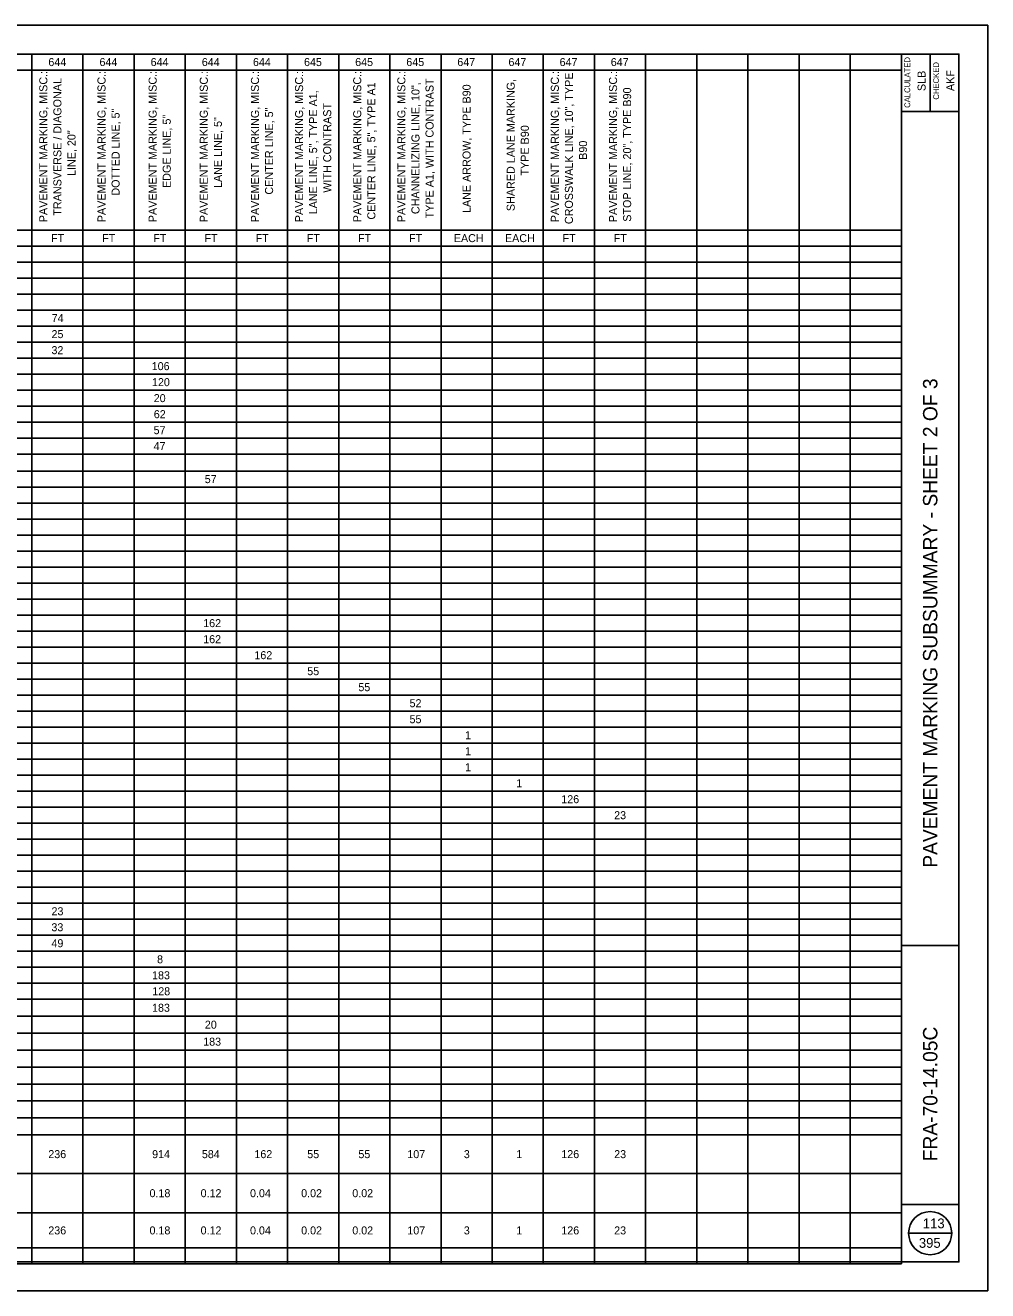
# Model space of a CAD drawing. Extents: x 1822379 to 1824724, y 710341 to 711455.
# Drawn here: x 1822396.38 to 1822413.11, y 711198.87 to 711220.87 of the extents above; entities that cross this region are included whole.
import ezdxf

# ---------------------------------------------------------------- set-up
doc = ezdxf.new("R2010")
doc.units = 0
for name, color, linetype in [('SH_Border', 7, 'Continuous'), ('SH_Cut_Line', 7, 'Continuous'), ('SH_Data', 7, 'Continuous'), ('SH_Text', 7, 'Continuous'), ('TX_P_20', 7, 'Continuous')]:
    doc.layers.add(name, color=color, linetype=linetype)

msp = doc.modelspace()

# ---------------------------------------------------------------- linework, layer by layer
at = {"layer": 'SH_Border'}
for p, q in [((1822411.613, 711199.366), (1822411.613, 711220.366)), ((1822412.113, 711220.366), (1822412.113, 711219.366)), ((1822411.613, 711219.366), (1822412.613, 711219.366)), ((1822411.613, 711204.866), (1822412.613, 711204.866)), ((1822411.613, 711200.366), (1822412.613, 711200.366))]:
    msp.add_line(p, q, dxfattribs=at)
msp.add_lwpolyline([(1822381.113, 711220.366), (1822412.613, 711220.366), (1822412.613, 711199.366), (1822381.113, 711199.366)], close=True, dxfattribs=at)
at = {"layer": 'SH_Cut_Line'}
msp.add_lwpolyline([(1822379.113, 711198.866), (1822413.113, 711198.866), (1822413.113, 711220.866), (1822379.113, 711220.866)], close=True, dxfattribs=at)
at = {"layer": 'SH_Data'}
for p, q in [((1822381.113, 711220.366), (1822411.613, 711220.366)), ((1822396.494, 711220.366), (1822396.494, 711199.333)), ((1822397.384, 711220.366), (1822397.384, 711199.333)), ((1822398.273, 711220.366), (1822398.273, 711199.333)), ((1822399.162, 711220.366), (1822399.162, 711199.333)), ((1822400.052, 711220.366), (1822400.052, 711199.333)), ((1822400.941, 711220.366), (1822400.941, 711199.333)), ((1822401.83, 711220.366), (1822401.83, 711199.333)), ((1822402.719, 711220.366), (1822402.719, 711199.333)), ((1822403.609, 711220.366), (1822403.609, 711199.333)), ((1822404.498, 711220.366), (1822404.498, 711199.333)), ((1822405.387, 711220.366), (1822405.387, 711199.333)), ((1822406.277, 711220.366), (1822406.277, 711199.333)), ((1822407.166, 711220.366), (1822407.166, 711199.333)), ((1822408.055, 711220.366), (1822408.055, 711199.333)), ((1822408.945, 711220.366), (1822408.945, 711199.333)), ((1822409.834, 711220.366), (1822409.834, 711199.333)), ((1822410.723, 711220.366), (1822410.723, 711199.333)), ((1822411.613, 711220.366), (1822411.613, 711199.333)), ((1822390.269, 711220.087), (1822411.613, 711220.087)), ((1822390.269, 711217.305), (1822411.613, 711217.305)), ((1822381.113, 711217.027), (1822411.613, 711217.027)), ((1822381.113, 711216.748), (1822411.613, 711216.748)), ((1822381.113, 711216.47), (1822411.613, 711216.47)), ((1822381.113, 711216.192), (1822411.613, 711216.192)), ((1822381.113, 711215.913), (1822411.613, 711215.913)), ((1822381.113, 711215.635), (1822411.613, 711215.635)), ((1822381.113, 711215.357), (1822411.613, 711215.357)), ((1822381.113, 711215.079), (1822411.613, 711215.079)), ((1822381.113, 711214.8), (1822411.613, 711214.8)), ((1822381.113, 711214.522), (1822411.613, 711214.522)), ((1822381.113, 711214.244), (1822411.613, 711214.244)), ((1822381.113, 711213.966), (1822411.613, 711213.966)), ((1822381.113, 711213.687), (1822411.613, 711213.687)), ((1822381.113, 711213.409), (1822411.613, 711213.409)), ((1822381.113, 711213.115), (1822411.613, 711213.115)), ((1822381.113, 711212.836), (1822411.613, 711212.836)), ((1822381.113, 711212.558), (1822411.613, 711212.558)), ((1822381.113, 711212.28), (1822411.613, 711212.28)), ((1822381.113, 711212.002), (1822411.613, 711212.002)), ((1822381.113, 711211.723), (1822411.613, 711211.723)), ((1822381.113, 711211.445), (1822411.613, 711211.445)), ((1822381.113, 711211.167), (1822411.613, 711211.167)), ((1822381.113, 711210.889), (1822411.613, 711210.889)), ((1822381.113, 711210.61), (1822411.613, 711210.61)), ((1822381.113, 711210.332), (1822411.613, 711210.332)), ((1822381.113, 711210.054), (1822411.613, 711210.054)), ((1822381.113, 711209.776), (1822411.613, 711209.776)), ((1822381.113, 711209.497), (1822411.613, 711209.497)), ((1822381.113, 711209.219), (1822411.613, 711209.219)), ((1822381.113, 711208.941), (1822411.613, 711208.941)), ((1822381.113, 711208.663), (1822411.613, 711208.663)), ((1822381.113, 711208.384), (1822411.613, 711208.384)), ((1822381.113, 711208.106), (1822411.613, 711208.106)), ((1822381.113, 711207.828), (1822411.613, 711207.828)), ((1822381.113, 711207.55), (1822411.613, 711207.55)), ((1822381.113, 711207.271), (1822411.613, 711207.271)), ((1822381.113, 711206.993), (1822411.613, 711206.993)), ((1822381.113, 711206.715), (1822411.613, 711206.715)), ((1822381.113, 711206.436), (1822411.613, 711206.436)), ((1822381.113, 711206.158), (1822411.613, 711206.158)), ((1822381.113, 711205.88), (1822411.613, 711205.88)), ((1822381.113, 711205.602), (1822411.613, 711205.602)), ((1822381.113, 711205.323), (1822411.613, 711205.323)), ((1822381.113, 711205.045), (1822411.613, 711205.045)), ((1822381.113, 711204.767), (1822411.613, 711204.767)), ((1822381.113, 711204.489), (1822411.613, 711204.489)), ((1822381.113, 711204.21), (1822411.613, 711204.21)), ((1822381.113, 711203.932), (1822411.613, 711203.932)), ((1822381.113, 711203.638), (1822411.613, 711203.638)), ((1822381.113, 711203.343), (1822411.613, 711203.343)), ((1822381.113, 711203.048), (1822411.613, 711203.048)), ((1822381.113, 711202.754), (1822411.613, 711202.754)), ((1822381.113, 711202.459), (1822411.613, 711202.459)), ((1822381.113, 711202.164), (1822411.613, 711202.164)), ((1822381.113, 711201.87), (1822411.613, 711201.87)), ((1822381.113, 711201.575), (1822411.613, 711201.575)), ((1822381.113, 711200.904), (1822411.613, 711200.904)), ((1822381.113, 711200.217), (1822411.613, 711200.217)), ((1822411.738, 711199.866), (1822412.488, 711199.866)), ((1822381.113, 711199.611), (1822411.613, 711199.611)), ((1822381.113, 711199.333), (1822411.613, 711199.333))]:
    msp.add_line(p, q, dxfattribs=at)
msp.add_circle((1822412.113, 711199.866), 0.375, dxfattribs=at)

# ---------------------------------------------------------------- texts
for s, height, p in [('CALCULATED', 0.1, (1822411.765, 711219.43)), ('CHECKED', 0.1, (1822412.265, 711219.573)), ('SLB', 0.14, (1822412.033, 711219.722)), ('AKF', 0.14, (1822412.533, 711219.723)), ('PAVEMENT MARKING SUBSUMMARY - SHEET 2 OF 3', 0.25, (1822412.238, 711206.219)), ('FRA-70-14.05C', 0.25, (1822412.238, 711201.115))]:
    msp.add_text(s, height=height, rotation=90, dxfattribs=at).set_placement(p)
at = {"layer": 'SH_Text'}
for s, height, p in [('644', 0.1391, (1822396.782, 711220.157)), ('644', 0.1391, (1822397.671, 711220.157)), ('644', 0.1391, (1822398.56, 711220.157)), ('644', 0.1391, (1822399.45, 711220.157)), ('644', 0.1391, (1822400.339, 711220.157)), ('645', 0.1391, (1822401.227, 711220.157)), ('645', 0.1391, (1822402.116, 711220.157)), ('645', 0.1391, (1822403.005, 711220.157)), ('647', 0.1391, (1822403.892, 711220.157)), ('647', 0.1391, (1822404.781, 711220.157)), ('647', 0.1391, (1822405.67, 711220.157)), ('647', 0.1391, (1822406.56, 711220.157)), ('FT', 0.1391, (1822396.829, 711217.096)), ('FT', 0.1391, (1822397.718, 711217.096)), ('FT', 0.1391, (1822398.607, 711217.096)), ('FT', 0.1391, (1822399.497, 711217.096)), ('FT', 0.1391, (1822400.386, 711217.096)), ('FT', 0.1391, (1822401.275, 711217.096)), ('FT', 0.1391, (1822402.165, 711217.096)), ('FT', 0.1391, (1822403.054, 711217.096)), ('EACH', 0.1391, (1822403.832, 711217.096)), ('EACH', 0.1391, (1822404.721, 711217.096)), ('FT', 0.1391, (1822405.722, 711217.096)), ('FT', 0.1391, (1822406.611, 711217.096)), ('74', 0.1391, (1822396.839, 711215.705)), ('25', 0.1391, (1822396.837, 711215.427)), ('32', 0.1391, (1822396.836, 711215.148)), ('106', 0.1391, (1822398.579, 711214.87)), ('120', 0.1391, (1822398.584, 711214.592)), ('20', 0.1391, (1822398.614, 711214.314)), ('62', 0.1391, (1822398.615, 711214.035)), ('57', 0.1391, (1822398.612, 711213.757)), ('47', 0.1391, (1822398.611, 711213.479)), ('57', 0.1391, (1822399.501, 711212.906)), ('162', 0.1391, (1822399.474, 711210.402)), ('162', 0.1391, (1822399.474, 711210.123)), ('162', 0.1391, (1822400.364, 711209.845)), ('55', 0.1391, (1822401.283, 711209.567)), ('55', 0.1391, (1822402.172, 711209.289)), ('52', 0.1391, (1822403.062, 711209.01)), ('55', 0.1391, (1822403.061, 711208.732)), ('1', 0.139, (1822404.027, 711208.454)), ('1', 0.139, (1822404.027, 711208.176)), ('1', 0.139, (1822404.027, 711207.897)), ('1', 0.139, (1822404.917, 711207.619)), ('126', 0.1391, (1822405.7, 711207.341)), ('23', 0.1391, (1822406.619, 711207.063)), ('23', 0.1391, (1822396.837, 711205.393)), ('33', 0.1391, (1822396.835, 711205.115)), ('49', 0.1391, (1822396.836, 711204.837)), ('8', 0.139, (1822398.672, 711204.558)), ('183', 0.1391, (1822398.585, 711204.28)), ('128', 0.1391, (1822398.589, 711204.002)), ('183', 0.1391, (1822398.585, 711203.715)), ('20', 0.1391, (1822399.503, 711203.421)), ('183', 0.1391, (1822399.474, 711203.126)), ('236', 0.1391, (1822396.781, 711201.17)), ('914', 0.1391, (1822398.586, 711201.17)), ('584', 0.1391, (1822399.451, 711201.17)), ('162', 0.1391, (1822400.364, 711201.17)), ('55', 0.1391, (1822401.283, 711201.17)), ('55', 0.1391, (1822402.172, 711201.17)), ('107', 0.1391, (1822403.023, 711201.17)), ('3', 0.139, (1822404.005, 711201.17)), ('1', 0.139, (1822404.917, 711201.17)), ('126', 0.1391, (1822405.7, 711201.17)), ('23', 0.1391, (1822406.619, 711201.17)), ('0.18', 0.1391, (1822398.541, 711200.491)), ('0.12', 0.1391, (1822399.429, 711200.491)), ('0.04', 0.1391, (1822400.288, 711200.491)), ('0.02', 0.1391, (1822401.177, 711200.491)), ('0.02', 0.1391, (1822402.066, 711200.491)), ('236', 0.1391, (1822396.781, 711199.844)), ('0.18', 0.1391, (1822398.541, 711199.844)), ('0.12', 0.1391, (1822399.429, 711199.844)), ('0.04', 0.1391, (1822400.288, 711199.844)), ('0.02', 0.1391, (1822401.177, 711199.844)), ('0.02', 0.1391, (1822402.066, 711199.844)), ('107', 0.1391, (1822403.023, 711199.844)), ('3', 0.139, (1822404.005, 711199.844)), ('1', 0.139, (1822404.917, 711199.844)), ('126', 0.1391, (1822405.7, 711199.844)), ('23', 0.1391, (1822406.619, 711199.844))]:
    msp.add_text(s, height=height, dxfattribs=at).set_placement(p)
for s, height, p in [('PAVEMENT MARKING, MISC.:', 0.13998, (1822396.764, 711217.442)), ('PAVEMENT MARKING, MISC.:', 0.13998, (1822397.776, 711217.442)), ('PAVEMENT MARKING, MISC.:', 0.13998, (1822398.665, 711217.442)), ('PAVEMENT MARKING, MISC.:', 0.13998, (1822399.554, 711217.442)), ('PAVEMENT MARKING, MISC.:', 0.13998, (1822400.444, 711217.442)), ('PAVEMENT MARKING, MISC.:', 0.13998, (1822401.211, 711217.442)), ('PAVEMENT MARKING, MISC.:', 0.13998, (1822402.222, 711217.442)), ('PAVEMENT MARKING, MISC.:', 0.13998, (1822402.989, 711217.442)), ('PAVEMENT MARKING, MISC.:', 0.13998, (1822405.657, 711217.442)), ('CROSSWALK LINE, 10", TYPE', 0.13998, (1822405.902, 711217.409)), ('PAVEMENT MARKING, MISC.:', 0.13998, (1822406.669, 711217.442)), ('TRANSVERSE / DIAGONAL', 0.13998, (1822397.009, 711217.556)), ('CENTER LINE, 5", TYPE A1', 0.13998, (1822402.467, 711217.488)), ('CHANNELIZING LINE, 10",', 0.13998, (1822403.234, 711217.583)), ('TYPE A1, WITH CONTRAST', 0.13998, (1822403.479, 711217.509)), ('LANE ARROW, TYPE B90', 0.13998, (1822404.123, 711217.602)), ('SHARED LANE MARKING,', 0.13998, (1822404.89, 711217.635)), ('STOP LINE, 20", TYPE B90', 0.13998, (1822406.914, 711217.45)), ('LANE LINE, 5", TYPE A1,', 0.13998, (1822401.455, 711217.579)), ('DOTTED LINE, 5"', 0.13998, (1822398.021, 711217.904)), ('EDGE LINE, 5"', 0.13998, (1822398.91, 711218.037)), ('CENTER LINE, 5"', 0.13998, (1822400.689, 711217.922)), ('WITH CONTRAST', 0.13998, (1822401.7, 711217.955)), ('LANE LINE, 5"', 0.13998, (1822399.799, 711218.037)), ('TYPE B90', 0.14, (1822405.135, 711218.254)), ('LINE, 20"', 0.14, (1822397.254, 711218.245)), ('B90', 0.14, (1822406.147, 711218.527))]:
    msp.add_text(s, height=height, rotation=90, dxfattribs=at).set_placement(p)
at = {"layer": 'TX_P_20'}
for s, p in [('113', (1822411.985, 711199.951)), ('395', (1822411.916, 711199.611))]:
    msp.add_text(s, height=0.17, dxfattribs=at).set_placement(p)

doc.saveas('drawing.dxf')
